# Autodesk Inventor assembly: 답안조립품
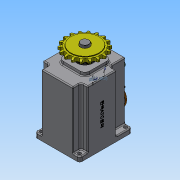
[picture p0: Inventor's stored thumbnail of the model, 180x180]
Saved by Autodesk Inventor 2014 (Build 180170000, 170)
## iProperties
Created: 2017-12
Part Number: 답안조립품
Document SubType Name: Assembly
Designer: 학생용
Mass: 1774.22 g
Surface Area: 2015.57 cm^2
Volume: 733.194 cm^3
Density: 2.41985 g/cm^3
Author: 학생용
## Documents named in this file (17)
- C:\Users\학생용\Desktop\371207V1024\답안조립품.iam
- C:\Users\학생용\Desktop\371207V1024\본체.ipt
- C:\Users\학생용\Desktop\371207V1024\부시.ipt
- C:\Users\학생용\Desktop\371207V1024\오일 실 17 32 8.ipt
- C:\Users\학생용\Desktop\371207V1024\커버.ipt
- C:\Users\학생용\Desktop\371207V1024\오일 실 8 22 7.ipt
- C:\Users\학생용\Desktop\371207V1024\베어링 608.ipt
- C:\Users\학생용\Desktop\371207V1024\베어링 6003.ipt
- C:\Users\학생용\Desktop\371207V1024\메인축.ipt
- C:\Users\학생용\Desktop\371207V1024\서브축.ipt
- C:\Users\학생용\Desktop\371207V1024\키 5 x 5 x 18.ipt
- C:\Users\학생용\Desktop\371207V1024\스프로킷.ipt
- C:\Users\학생용\Desktop\371207V1024\멈춤나사 M3x8.ipt
- C:\Users\학생용\Desktop\371207V1024\슬라이더.ipt
- C:\Users\학생용\Desktop\371207V1024\볼트 M4 x 10.ipt
- C:\Users\학생용\Desktop\371207V1024\상부 캡.ipt
- C:\Users\학생용\Desktop\371207V1024\가변스프링.ipt
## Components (1 placed, 1 different names)
1. 가변스프링:1
